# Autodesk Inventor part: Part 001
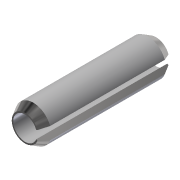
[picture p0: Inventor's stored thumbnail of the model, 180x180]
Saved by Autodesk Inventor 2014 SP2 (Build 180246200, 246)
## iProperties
Created: 2015-03
Part Number: Part 001
Material: Steel
Document SubType Name: Modeling
Designer: SFC-LNV
Mass: 0.908365 g
Surface Area: 3.51701 cm^2
Volume: 0.115715 cm^3
Density: 7.85 g/cm^3
Appearance: Steel - Polished
Author: SFC-LNV
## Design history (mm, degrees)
sketch "Sketch1"
  geometry: L1 (-8, 1.45)-(8, 1.45); L2 (8, 1.45)-(8, 1.623); L3 (8, 1.623)-(7, 2.2); L4 (7, 2.2)-(-7, 2.2); L5 (-7, 2.2)-(-8, 1.623); L6 (-8, 1.623)-(-8, 1.45); L7 (-11.2, 0)-(11.2, 0) reference; 3 further points
  constraints: 12 end point, 2 midpoint, 2 parallel, 2 vertical alignment, 1 equal length, 1 horizontal, 1 perpendicular
  dimensions: "d0" = 16 distance of L1.start L1.end; "d1" = 30 deg angle of L4 L5; "d2" = 1 horizontal distance of L4.end L5.end; "d3" = 4.4 diameter of L4 L7; "d4" = 0.75 distance between parallel lines of L1 L4
revolve "Revolution1" sketch "Sketch1" stored, may be unused: angle "d5" = 90 deg
sketch "Sketch2"
  geometry: L1 (0, 0)-(-1.361, 0.5); L2 (0, 0)-(-1.361, -0.5); L3 (-1.361, 0.5)-(-2.065, 0.759); L4 (-1.361, -0.5)-(-2.065, -0.759); L5 (3.101, 0)-(-3.209, 0) reference; A1 r 2.2 centre (0, 0) between (-2.065, 0.759) and (-2.065, -0.759) reference; A2 r 1.45 centre (0, 0) between (-1.361, 0.5) and (-1.361, -0.5) reference; A3 r 2.2 centre (0, 0) between (-2.065, 0.759) and (-2.065, -0.759); A4 r 1.45 centre (0, 0) between (-1.361, 0.5) and (-1.361, -0.5); 1 further point
  constraints: 8 end point, 8 point on circle, 2 centre point, 2 collinear, 2 concentric, 1 other
  dimensions: "d6" = 1 distance of L2.end L1.end
extrude "Extrusion1" cut sketch "Sketch2" stored distance "d7" = 10; taper "d8" = 0 deg
body "Solid1"
